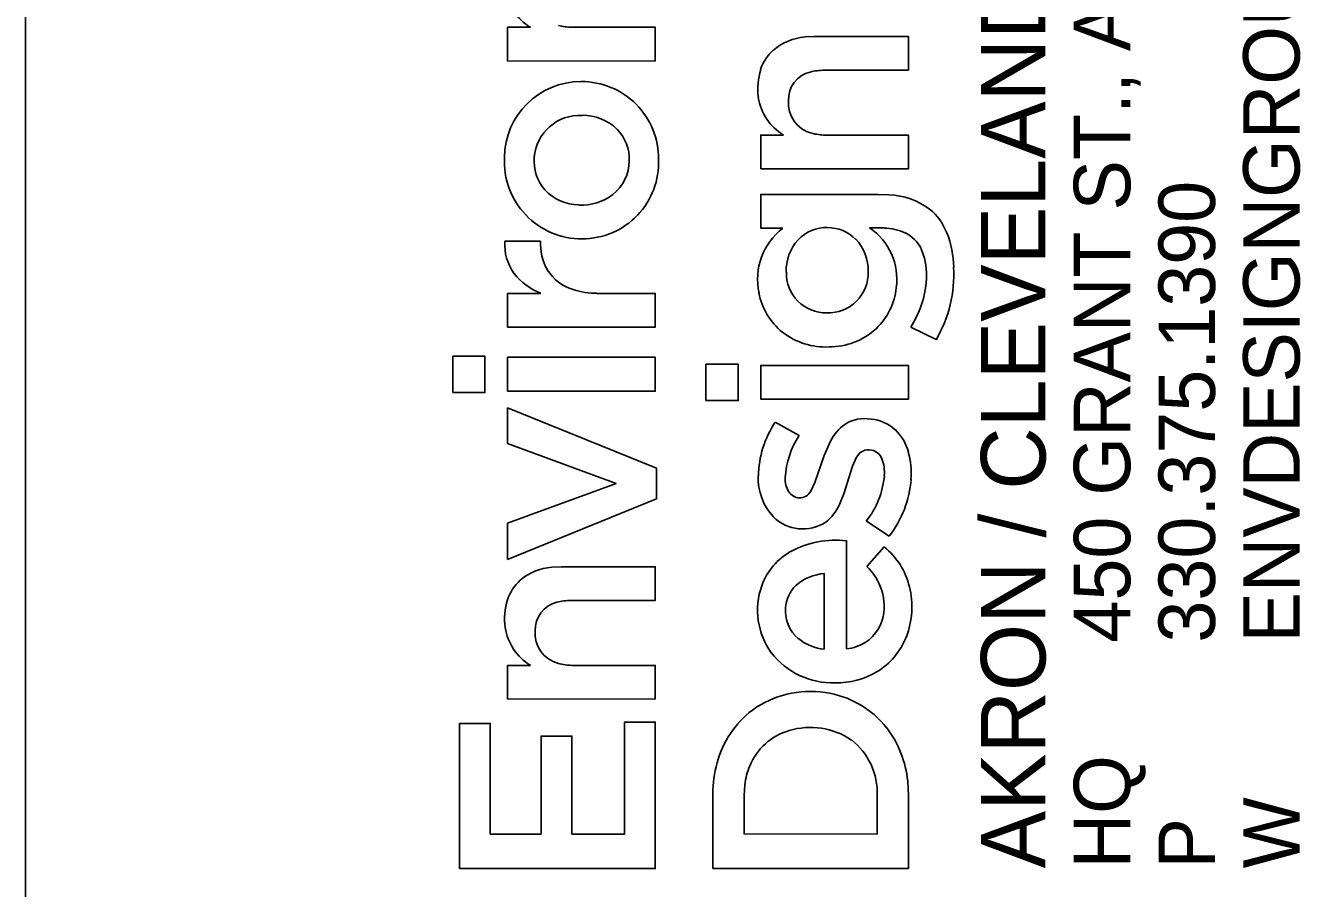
# Model space of a CAD drawing. Extents: x -6.7 to 34, y -1.6 to 22.
# Drawn here: x 32 to 33.125, y 3.12 to 3.882 of the extents above; entities that cross this region are included whole.
import ezdxf

# ---------------------------------------------------------------- set-up
doc = ezdxf.new("R2010")
doc.units = 0
doc.layers.add('SH_Border', color=7, linetype='Continuous')
doc.layers.add('SH_Data', color=7, linetype='Continuous')

msp = doc.modelspace()

# ---------------------------------------------------------------- linework, layer by layer
at = {"layer": 'SH_Border'}
msp.add_line((32, 0.5), (32, 21.5), dxfattribs=at)
at = {"layer": 'SH_Data'}
for p, q in [((32.4254, 3.8509), (32.4254, 3.8807)), ((32.4254, 3.8807), (32.4455, 3.8807)), ((32.4822, 3.8807), (32.5557, 3.8807)), ((32.5557, 3.8807), (32.5557, 3.851)), ((32.6878, 3.8722), (32.6963, 3.8727)), ((32.6963, 3.8727), (32.7792, 3.8727)), ((32.7792, 3.8727), (32.7792, 3.8429)), ((32.5557, 3.851), (32.4254, 3.8509)), ((32.7792, 3.8429), (32.7048, 3.8428)), ((32.6489, 3.7557), (32.6489, 3.7855)), ((32.6489, 3.7855), (32.669, 3.7855)), ((32.7057, 3.7855), (32.7791, 3.7855)), ((32.7791, 3.7855), (32.7792, 3.7558)), ((32.7792, 3.7558), (32.6489, 3.7557)), ((32.6489, 3.7034), (32.6489, 3.7332)), ((32.6489, 3.7332), (32.7524, 3.7332)), ((32.7524, 3.7332), (32.7619, 3.7329)), ((32.6684, 3.7034), (32.6489, 3.7034)), ((32.7576, 3.7036), (32.7449, 3.7036)), ((32.423, 3.6919), (32.4545, 3.6919)), ((32.4254, 3.6159), (32.4254, 3.6458)), ((32.4254, 3.6458), (32.4547, 3.6458)), ((32.5041, 3.6458), (32.5557, 3.6457)), ((32.5557, 3.6457), (32.5556, 3.6159)), ((32.5556, 3.6159), (32.4254, 3.6159)), ((32.8036, 3.6049), (32.7812, 3.616)), ((32.3771, 3.5582), (32.3771, 3.5903)), ((32.3771, 3.5903), (32.4054, 3.5903)), ((32.4054, 3.5903), (32.4054, 3.5582)), ((32.4254, 3.5594), (32.4254, 3.5893)), ((32.4254, 3.5893), (32.5557, 3.5893)), ((32.5557, 3.5893), (32.5557, 3.5594)), ((32.6005, 3.5511), (32.6005, 3.5832)), ((32.6005, 3.5832), (32.6289, 3.5832)), ((32.6289, 3.5832), (32.6289, 3.5511)), ((32.6489, 3.5523), (32.6489, 3.5822)), ((32.6489, 3.5822), (32.7792, 3.5822)), ((32.7792, 3.5822), (32.7792, 3.5523)), ((32.4054, 3.5582), (32.3771, 3.5582)), ((32.5557, 3.5594), (32.4254, 3.5594)), ((32.4254, 3.5133), (32.4254, 3.5446)), ((32.4254, 3.5446), (32.5567, 3.4913)), ((32.6289, 3.5511), (32.6005, 3.5511)), ((32.7792, 3.5523), (32.6489, 3.5523)), ((32.6615, 3.5321), (32.6827, 3.5203)), ((32.5212, 3.478), (32.4254, 3.5133)), ((32.7048, 3.5026), (32.7104, 3.5153)), ((32.6967, 3.4787), (32.7048, 3.5026)), ((32.7334, 3.501), (32.7298, 3.4933)), ((32.5567, 3.4913), (32.5567, 3.4644)), ((32.7298, 3.4933), (32.7221, 3.4688)), ((32.4254, 3.4429), (32.5212, 3.478)), ((32.693, 3.4712), (32.6967, 3.4787)), ((32.7221, 3.4688), (32.7182, 3.4592)), ((32.5567, 3.4644), (32.4254, 3.4109)), ((32.4254, 3.4109), (32.4254, 3.4429)), ((32.7621, 3.4314), (32.742, 3.4447)), ((32.7245, 3.4275), (32.7246, 3.3319)), ((32.7423, 3.4046), (32.7577, 3.422)), ((32.4644, 3.404), (32.4729, 3.4044)), ((32.4729, 3.4044), (32.5557, 3.4044)), ((32.5557, 3.4044), (32.5557, 3.3746)), ((32.7049, 3.3318), (32.7049, 3.3983)), ((32.5557, 3.3746), (32.4814, 3.3746)), ((32.7036, 3.3317), (32.7049, 3.3318)), ((32.4254, 3.2875), (32.4254, 3.3173)), ((32.4254, 3.3173), (32.4455, 3.3173)), ((32.4822, 3.3173), (32.5557, 3.3173)), ((32.5557, 3.3173), (32.5557, 3.2876)), ((32.5557, 3.2876), (32.4254, 3.2875)), ((32.383, 3.1379), (32.383, 3.266)), ((32.383, 3.266), (32.4101, 3.266)), ((32.4101, 3.266), (32.4101, 3.1683)), ((32.5286, 3.1683), (32.5286, 3.2672)), ((32.5286, 3.2672), (32.5557, 3.2672)), ((32.5557, 3.2672), (32.5557, 3.1379)), ((32.455, 3.1683), (32.455, 3.2549)), ((32.455, 3.2549), (32.4822, 3.2549)), ((32.4822, 3.2549), (32.4822, 3.1683)), ((32.6347, 3.2118), (32.6341, 3.2023)), ((32.7785, 3.215), (32.7792, 3.2021)), ((32.6064, 3.138), (32.6064, 3.204)), ((32.6341, 3.2023), (32.6341, 3.1684)), ((32.7515, 3.1683), (32.7515, 3.2024)), ((32.7792, 3.2021), (32.7792, 3.138)), ((32.4101, 3.1683), (32.455, 3.1683)), ((32.4822, 3.1683), (32.5286, 3.1683)), ((32.6341, 3.1684), (32.7515, 3.1683)), ((32.5557, 3.1379), (32.383, 3.1379)), ((32.7792, 3.138), (32.6064, 3.138))]:
    msp.add_line(p, q, dxfattribs=at)
for points in [[(32.4254, 3.8509), (32.4254, 3.8807), (32.4455, 3.8807)], [(32.4822, 3.8807), (32.5557, 3.8807), (32.5557, 3.851), (32.4254, 3.8509)], [(32.6878, 3.8722), (32.6963, 3.8727), (32.7792, 3.8727), (32.7792, 3.8429), (32.7048, 3.8428)], [(32.6489, 3.7557), (32.6489, 3.7855), (32.669, 3.7855)], [(32.7057, 3.7855), (32.7791, 3.7855), (32.7792, 3.7558), (32.6489, 3.7557)], [(32.6684, 3.7034), (32.6489, 3.7034), (32.6489, 3.7332), (32.7524, 3.7332), (32.7619, 3.7329)], [(32.7576, 3.7036), (32.7449, 3.7036)], [(32.423, 3.6919), (32.4545, 3.6919)], [(32.4254, 3.6159), (32.4254, 3.6458), (32.4547, 3.6458)], [(32.5041, 3.6458), (32.5557, 3.6457), (32.5556, 3.6159), (32.4254, 3.6159)], [(32.8036, 3.6049), (32.7812, 3.616)], [(32.6615, 3.5321), (32.6827, 3.5203)], [(32.693, 3.4712), (32.6967, 3.4787), (32.7048, 3.5026), (32.7104, 3.5153)], [(32.7334, 3.501), (32.7298, 3.4933), (32.7221, 3.4688), (32.7182, 3.4592)], [(32.7621, 3.4314), (32.742, 3.4447)], [(32.7245, 3.4275), (32.7246, 3.3319)], [(32.7423, 3.4046), (32.7577, 3.422)], [(32.4644, 3.404), (32.4729, 3.4044), (32.5557, 3.4044), (32.5557, 3.3746), (32.4814, 3.3746)], [(32.7036, 3.3317), (32.7049, 3.3318), (32.7049, 3.3983)], [(32.4254, 3.2875), (32.4254, 3.3173), (32.4455, 3.3173)], [(32.4822, 3.3173), (32.5557, 3.3173), (32.5557, 3.2876), (32.4254, 3.2875)], [(32.7785, 3.215), (32.7792, 3.2021), (32.7792, 3.138), (32.6064, 3.138)], [(32.6347, 3.2118), (32.6341, 3.2023), (32.6341, 3.1684), (32.7515, 3.1683), (32.7515, 3.2024)], [(32.6064, 3.138), (32.6064, 3.204)]]:
    msp.add_lwpolyline(points, dxfattribs=at)
for points in [[(32.3771, 3.5582), (32.3771, 3.5903), (32.4054, 3.5903), (32.4054, 3.5582)], [(32.4254, 3.5594), (32.4254, 3.5893), (32.5557, 3.5893), (32.5557, 3.5594)], [(32.6005, 3.5511), (32.6005, 3.5832), (32.6289, 3.5832), (32.6289, 3.5511)], [(32.6489, 3.5523), (32.6489, 3.5822), (32.7792, 3.5822), (32.7792, 3.5523)], [(32.4254, 3.4109), (32.4254, 3.4429), (32.5212, 3.478), (32.4254, 3.5133), (32.4254, 3.5446), (32.5567, 3.4913), (32.5567, 3.4644)], [(32.383, 3.1379), (32.383, 3.266), (32.4101, 3.266), (32.4101, 3.1683), (32.455, 3.1683), (32.455, 3.2549), (32.4822, 3.2549), (32.4822, 3.1683), (32.5286, 3.1683), (32.5286, 3.2672), (32.5557, 3.2672), (32.5557, 3.1379)]]:
    msp.add_lwpolyline(points, close=True, dxfattribs=at)
for centre, radius, start, end in [((32.4703, 3.9214), 0.0476, 188.9646, 238.6987), ((32.4703, 3.9214), 0.0476, 188.9646, 238.6987), ((32.4818, 3.9229), 0.0421, 254.0891, 270.5284), ((32.4818, 3.9229), 0.0421, 254.0891, 270.5284), ((32.6922, 3.8225), 0.0499, 94.9706, 130.2248), ((32.6922, 3.8225), 0.0499, 94.9706, 130.2248), ((32.6869, 3.8309), 0.0402, 132.2238, 161.6823), ((32.6869, 3.8309), 0.0402, 132.2238, 161.6823), ((32.7022, 3.8264), 0.056, 162.274, 187.7917), ((32.7022, 3.8264), 0.056, 162.274, 187.7917), ((32.6983, 3.8169), 0.025, 103.6868, 182.214), ((32.6983, 3.8169), 0.025, 103.6868, 182.214), ((32.7045, 3.7968), 0.046, 89.6051, 105.3303), ((32.7045, 3.7968), 0.046, 89.6051, 105.3303), ((32.4901, 3.7654), 0.0674, 89.8476, 179.6405), ((32.4901, 3.7654), 0.0674, 89.8476, 179.6405), ((32.4906, 3.7647), 0.0681, 359.5401, 90.2114), ((32.4906, 3.7647), 0.0681, 359.5401, 90.2114), ((32.6937, 3.8262), 0.0476, 188.9646, 238.6987), ((32.6937, 3.8262), 0.0476, 188.9646, 238.6987), ((32.7008, 3.8138), 0.0276, 175.5844, 255.1382), ((32.7008, 3.8138), 0.0276, 175.5844, 255.1382), ((32.4892, 3.7626), 0.0404, 87.0481, 175.5726), ((32.4892, 3.7626), 0.0404, 87.0481, 175.5726), ((32.492, 3.76), 0.043, 45.8426, 90.9801), ((32.492, 3.76), 0.043, 45.8426, 90.9801), ((32.4946, 3.7642), 0.0382, 357.8857, 44.159), ((32.4946, 3.7642), 0.0382, 357.8857, 44.159), ((32.7053, 3.8277), 0.0421, 254.0891, 270.5284), ((32.7053, 3.8277), 0.0421, 254.0891, 270.5284), ((32.4908, 3.7621), 0.0682, 176.8344, 270.4038), ((32.4908, 3.7621), 0.0682, 176.8344, 270.4038), ((32.4873, 3.7625), 0.0385, 175.1538, 221.1471), ((32.4873, 3.7625), 0.0385, 175.1538, 221.1471), ((32.4912, 3.7614), 0.0675, 270.0624, 2.3776), ((32.4912, 3.7614), 0.0675, 270.0624, 2.3776), ((32.4945, 3.7632), 0.0383, 308.2894, 359.4347), ((32.4945, 3.7632), 0.0383, 308.2894, 359.4347), ((32.4892, 3.7661), 0.0423, 223.0999, 268.8089), ((32.4892, 3.7661), 0.0423, 223.0999, 268.8089), ((32.491, 3.7679), 0.0442, 266.5651, 308.0608), ((32.491, 3.7679), 0.0442, 266.5651, 308.0608), ((32.7591, 3.6679), 0.065, 53.4034, 87.4906), ((32.7591, 3.6679), 0.065, 53.4034, 87.4906), ((32.7652, 3.6804), 0.0514, 21.6075, 50.5577), ((32.7652, 3.6804), 0.0514, 21.6075, 50.5577), ((32.7029, 3.6581), 0.0569, 127.3748, 192.2247), ((32.7029, 3.6581), 0.0569, 127.3748, 192.2247), ((32.7069, 3.6693), 0.0346, 88.473, 136.4256), ((32.7069, 3.6693), 0.0346, 88.473, 136.4256), ((32.7081, 3.6696), 0.0342, 44.2719, 90.4762), ((32.7081, 3.6696), 0.0342, 44.2719, 90.4762), ((32.7142, 3.6583), 0.0547, 352.1125, 55.923), ((32.7142, 3.6583), 0.0547, 352.1125, 55.923), ((32.7567, 3.6572), 0.0463, 65.0169, 88.8011), ((32.7567, 3.6572), 0.0463, 65.0169, 88.8011), ((32.4662, 3.6888), 0.0433, 175.8731, 216.3475), ((32.4662, 3.6888), 0.0433, 175.8731, 216.3475), ((32.5009, 3.6895), 0.0464, 176.9688, 209.6064), ((32.5009, 3.6895), 0.0464, 176.9688, 209.6064), ((32.7114, 3.666), 0.0401, 137.4674, 182.3324), ((32.7114, 3.666), 0.0401, 137.4674, 182.3324), ((32.7037, 3.666), 0.04, 358.5714, 43.5376), ((32.7037, 3.666), 0.04, 358.5714, 43.5376), ((32.7626, 3.6716), 0.0309, 26.2681, 63.803), ((32.7626, 3.6716), 0.0309, 26.2681, 63.803), ((32.7307, 3.6671), 0.0884, 1.1514, 21.3627), ((32.7307, 3.6671), 0.0884, 1.1514, 21.3627), ((32.7357, 3.6615), 0.0595, 349.3073, 23.4307), ((32.7357, 3.6615), 0.0595, 349.3073, 23.4307), ((32.7054, 3.6624), 0.1138, 329.6388, 3.26), ((32.7054, 3.6624), 0.1138, 329.6388, 3.26), ((32.4747, 3.6972), 0.0551, 218.0981, 248.7907), ((32.4747, 3.6972), 0.0551, 218.0981, 248.7907), ((32.4951, 3.6881), 0.0408, 211.9447, 253.2028), ((32.4951, 3.6881), 0.0408, 211.9447, 253.2028), ((32.7065, 3.6637), 0.0351, 178.8821, 271.0837), ((32.7065, 3.6637), 0.0351, 178.8821, 271.0837), ((32.7082, 3.664), 0.0355, 268.2788, 1.5502), ((32.7082, 3.664), 0.0355, 268.2788, 1.5502), ((32.5047, 3.7165), 0.0707, 252.4655, 269.573), ((32.5047, 3.7165), 0.0707, 252.4655, 269.573), ((32.7046, 3.657), 0.0584, 190.7518, 231.2892), ((32.7046, 3.657), 0.0584, 190.7518, 231.2892), ((32.7099, 3.6571), 0.0589, 313.742, 353.8554), ((32.7099, 3.6571), 0.0589, 313.742, 353.8554), ((32.7074, 3.6633), 0.0877, 327.3149, 351.5748), ((32.7074, 3.6633), 0.0877, 327.3149, 351.5748), ((32.7095, 3.659), 0.0605, 269.6361, 312.7088), ((32.7095, 3.659), 0.0605, 269.6361, 312.7088), ((32.7063, 3.6611), 0.0627, 232.4606, 272.5902), ((32.7063, 3.6611), 0.0627, 232.4606, 272.5902), ((32.7406, 3.5026), 0.0326, 80.1719, 122.5197), ((32.7406, 3.5026), 0.0326, 80.1719, 122.5197), ((32.7428, 3.4982), 0.0367, 47.7934, 84.6892), ((32.7428, 3.4982), 0.0367, 47.7934, 84.6892), ((32.7364, 3.4826), 0.0897, 146.531, 178.7571), ((32.7364, 3.4826), 0.0897, 146.531, 178.7571), ((32.7466, 3.4971), 0.0405, 125.5118, 153.4159), ((32.7466, 3.4971), 0.0405, 125.5118, 153.4159), ((32.7379, 3.4946), 0.0427, 14.9966, 46.2063), ((32.7379, 3.4946), 0.0427, 14.9966, 46.2063), ((32.7452, 3.4789), 0.0749, 146.5112, 176.9101), ((32.7452, 3.4789), 0.0749, 146.5112, 176.9101), ((32.7438, 3.4963), 0.0114, 76.6609, 155.7053), ((32.7438, 3.4963), 0.0114, 76.6609, 155.7053), ((32.744, 3.4951), 0.0126, 21.5098, 78.5262), ((32.744, 3.4951), 0.0126, 21.5098, 78.5262), ((32.7259, 3.4877), 0.0321, 354.5726, 22.068), ((32.7259, 3.4877), 0.0321, 354.5726, 22.068), ((32.7104, 3.4867), 0.0712, 355.8306, 15.3914), ((32.7104, 3.4867), 0.0712, 355.8306, 15.3914), ((32.6967, 3.4824), 0.0501, 177.5366, 222.7932), ((32.6967, 3.4824), 0.0501, 177.5366, 222.7932), ((32.6931, 3.4823), 0.0228, 178.4747, 211.0868), ((32.6931, 3.4823), 0.0228, 178.4747, 211.0868), ((32.6825, 3.4915), 0.0757, 321.811, 354.7969), ((32.6825, 3.4915), 0.0757, 321.811, 354.7969), ((32.6895, 3.4882), 0.0922, 321.9777, 355.8738), ((32.6895, 3.4882), 0.0922, 321.9777, 355.8738), ((32.6833, 3.4767), 0.0115, 212.2368, 268.3777), ((32.6833, 3.4767), 0.0115, 212.2368, 268.3777), ((32.6834, 3.4759), 0.0107, 267.716, 333.7337), ((32.6834, 3.4759), 0.0107, 267.716, 333.7337), ((32.681, 3.4758), 0.0408, 308.0877, 335.9874), ((32.681, 3.4758), 0.0408, 308.0877, 335.9874), ((32.686, 3.4753), 0.0375, 225.9854, 302.4797), ((32.686, 3.4753), 0.0375, 225.9854, 302.4797), ((32.7152, 3.3441), 0.0838, 83.615, 118.2876), ((32.7152, 3.3441), 0.0838, 83.615, 118.2876), ((32.7174, 3.3717), 0.0644, 13.5336, 51.3615), ((32.7174, 3.3717), 0.0644, 13.5336, 51.3615), ((32.7024, 3.3691), 0.0558, 118.8308, 160.6244), ((32.7024, 3.3691), 0.0558, 118.8308, 160.6244), ((32.4687, 3.3543), 0.0499, 94.9696, 130.2225), ((32.4687, 3.3543), 0.0499, 94.9696, 130.2225), ((32.7079, 3.3561), 0.0424, 94.008, 130.8817), ((32.7079, 3.3561), 0.0424, 94.008, 130.8817), ((32.7038, 3.3656), 0.0549, 19.0357, 45.4406), ((32.7038, 3.3656), 0.0549, 19.0357, 45.4406), ((32.4635, 3.3626), 0.0402, 132.2219, 161.6818), ((32.4635, 3.3626), 0.0402, 132.2219, 161.6818), ((32.7104, 3.3661), 0.0644, 160.5201, 215.7831), ((32.7104, 3.3661), 0.0644, 160.5201, 215.7831), ((32.7005, 3.3663), 0.0298, 132.9851, 177.179), ((32.7005, 3.3663), 0.0298, 132.9851, 177.179), ((32.7064, 3.3692), 0.0758, 339.3542, 13.3785), ((32.7064, 3.3692), 0.0758, 339.3542, 13.3785), ((32.7107, 3.3697), 0.047, 344.6059, 17.007), ((32.7107, 3.3697), 0.047, 344.6059, 17.007), ((32.4787, 3.3582), 0.056, 162.2736, 187.7919), ((32.4787, 3.3582), 0.056, 162.2736, 187.7919), ((32.4748, 3.3487), 0.025, 103.6865, 182.2187), ((32.4748, 3.3487), 0.025, 103.6865, 182.2187), ((32.4811, 3.3286), 0.046, 89.6049, 105.3284), ((32.4811, 3.3286), 0.046, 89.6049, 105.3284), ((32.7017, 3.365), 0.0311, 175.0013, 223.283), ((32.7017, 3.365), 0.0311, 175.0013, 223.283), ((32.7224, 3.3671), 0.035, 288.0077, 343.5508), ((32.7224, 3.3671), 0.035, 288.0077, 343.5508), ((32.4703, 3.358), 0.0476, 188.962, 238.7037), ((32.4703, 3.358), 0.0476, 188.962, 238.7037), ((32.4773, 3.3456), 0.0276, 175.5854, 255.1439), ((32.4773, 3.3456), 0.0276, 175.5854, 255.1439), ((32.7089, 3.3736), 0.0423, 225.0619, 262.7974), ((32.7089, 3.3736), 0.0423, 225.0619, 262.7974), ((32.7189, 3.3652), 0.0626, 300.9427, 338.7323), ((32.7189, 3.3652), 0.0626, 300.9427, 338.7323), ((32.7247, 3.3522), 0.0202, 269.7003, 294.8711), ((32.7247, 3.3522), 0.0202, 269.7003, 294.8711), ((32.7125, 3.3705), 0.0687, 217.7452, 271.6543), ((32.7125, 3.3705), 0.0687, 217.7452, 271.6543), ((32.4818, 3.3595), 0.0422, 254.0916, 270.5284), ((32.4818, 3.3595), 0.0422, 254.0916, 270.5284), ((32.7155, 3.3724), 0.0706, 269.2048, 300.3341), ((32.7155, 3.3724), 0.0706, 269.2048, 300.3341), ((32.6923, 3.2079), 0.0864, 81.194, 125.9984), ((32.6923, 3.2079), 0.0864, 81.194, 125.9984), ((32.6946, 3.2113), 0.0827, 37.8521, 82.402), ((32.6946, 3.2113), 0.0827, 37.8521, 82.402), ((32.6939, 3.2089), 0.0865, 127.2362, 165.148), ((32.6939, 3.2089), 0.0865, 127.2362, 165.148), ((32.6889, 3.2078), 0.054, 106.1881, 157.3861), ((32.6889, 3.2078), 0.054, 106.1881, 157.3861), ((32.6928, 3.1986), 0.0639, 55.6727, 107.2093), ((32.6928, 3.1986), 0.0639, 55.6727, 107.2093), ((32.6859, 3.2057), 0.0931, 5.7333, 37.304), ((32.6859, 3.2057), 0.0931, 5.7333, 37.304), ((32.6929, 3.205), 0.0587, 357.4662, 52.2665), ((32.6929, 3.205), 0.0587, 357.4662, 52.2665), ((32.7143, 3.2028), 0.1078, 164.7861, 179.3704), ((32.7143, 3.2028), 0.1078, 164.7861, 179.3704), ((32.6983, 3.2039), 0.0641, 157.3571, 172.9275), ((32.6983, 3.2039), 0.0641, 157.3571, 172.9275)]:
    msp.add_arc(centre, radius, start, end, dxfattribs=at)

# ---------------------------------------------------------------- texts
for s, height, p in [('450 GRANT ST., AKRON, OH  44311', 0.049846, (32.9749, 3.3374)), ('AKRON / CLEVELAND / COLUMBUS', 0.056969, (32.9001, 3.138)), ('ENVDESIGNGROUP.COM', 0.049846, (33.1244, 3.3374)), ('330.375.1390', 0.049846, (33.0497, 3.3374)), ('HQ ', 0.04985, (32.9749, 3.138)), ('W', 0.0498, (33.1244, 3.138)), ('P', 0.0498, (33.0497, 3.138))]:
    msp.add_text(s, height=height, rotation=90, dxfattribs=at).set_placement(p)

doc.saveas('drawing.dxf')
